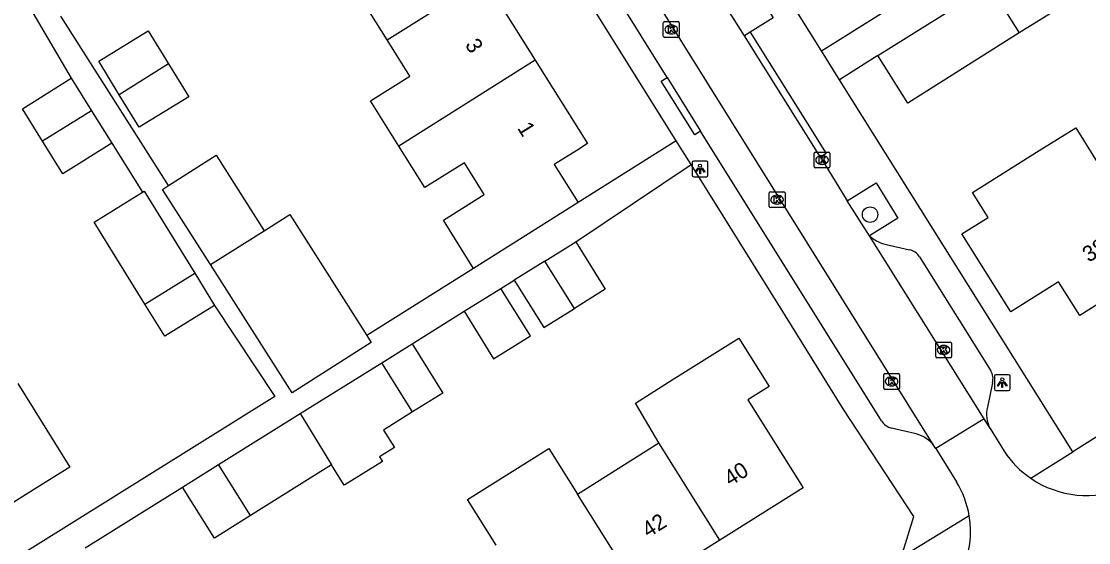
# Model space of a CAD drawing. Extents: x 159353 to 160616, y 385893 to 387321.
# Drawn here: x 159730.6 to 159798.3, y 386120.3 to 386153.3 of the extents above; entities that cross this region are included whole.
import ezdxf

# ---------------------------------------------------------------- set-up
doc = ezdxf.new("R2010")
doc.units = 0
for name, color, linetype in [('IMGEO_Boom', 7, 'Continuous'), ('IMGEO_Kolk', 7, 'Continuous'), ('IMGEO_Lichtpunt', 7, 'Continuous'), ('IMGEO_Pand', 7, 'Continuous'), ('IMGEO_Pand_nummerreeks', 7, 'Continuous'), ('IMGEO_Rijbaan_lokaal_open', 7, 'Continuous'), ('IMGEO_Voetpad_open', 7, 'Continuous')]:
    doc.layers.add(name, color=color, linetype=linetype)

msp = doc.modelspace()

# ---------------------------------------------------------------- linework, layer by layer
at = {"layer": 'IMGEO_Boom'}
msp.add_circle((159784.403, 386141.074), 0.489, dxfattribs=at)
at = {"layer": 'IMGEO_Kolk'}
for p, q in [((159771.291, 386152.384), (159771.291, 386153.236)), ((159771.366, 386153.31), (159772.218, 386153.31)), ((159771.779, 386153.09), (159771.804, 386153.09)), ((159772.292, 386153.236), (159772.292, 386152.384)), ((159772.218, 386152.31), (159771.366, 386152.31)), ((159771.802, 386152.53), (159771.777, 386152.53)), ((159780.853, 386144.115), (159780.853, 386144.967)), ((159780.928, 386145.041), (159781.78, 386145.041)), ((159781.341, 386144.821), (159781.366, 386144.821)), ((159781.854, 386144.967), (159781.854, 386144.115)), ((159781.364, 386144.261), (159781.339, 386144.261)), ((159781.78, 386144.041), (159780.928, 386144.041)), ((159778.006, 386141.598), (159778.006, 386142.45)), ((159778.081, 386142.524), (159778.933, 386142.524)), ((159778.494, 386142.304), (159778.519, 386142.304)), ((159779.007, 386142.45), (159779.007, 386141.598)), ((159778.933, 386141.524), (159778.081, 386141.524)), ((159778.517, 386141.744), (159778.492, 386141.744)), ((159788.563, 386132.072), (159788.563, 386132.924)), ((159788.638, 386132.998), (159789.49, 386132.998)), ((159789.051, 386132.778), (159789.076, 386132.778)), ((159789.564, 386132.924), (159789.564, 386132.072)), ((159789.49, 386131.998), (159788.638, 386131.998)), ((159789.074, 386132.218), (159789.049, 386132.218)), ((159785.265, 386130.071), (159785.265, 386130.923)), ((159785.34, 386130.997), (159786.192, 386130.997)), ((159785.753, 386130.777), (159785.778, 386130.777)), ((159786.266, 386130.923), (159786.266, 386130.071)), ((159786.192, 386129.997), (159785.34, 386129.997)), ((159785.776, 386130.217), (159785.751, 386130.217))]:
    msp.add_line(p, q, dxfattribs=at)
for points in [[(159771.291, 386152.384), (159771.291, 386153.236)], [(159771.366, 386153.31), (159772.218, 386153.31)], [(159771.612, 386153.01), (159771.735, 386153.01), (159771.735, 386152.859), (159771.865, 386153.01), (159772.029, 386153.01), (159771.883, 386152.859), (159772.036, 386152.61), (159771.884, 386152.61), (159771.799, 386152.774), (159771.735, 386152.707), (159771.735, 386152.61), (159771.612, 386152.61), (159771.612, 386153.01)], [(159772.292, 386153.236), (159772.292, 386152.384)], [(159772.218, 386152.31), (159771.366, 386152.31)], [(159780.853, 386144.115), (159780.853, 386144.967)], [(159780.928, 386145.041), (159781.78, 386145.041)], [(159781.854, 386144.967), (159781.854, 386144.115)], [(159781.174, 386144.741), (159781.297, 386144.741), (159781.297, 386144.59), (159781.427, 386144.741), (159781.591, 386144.741), (159781.445, 386144.59), (159781.598, 386144.341), (159781.446, 386144.341), (159781.361, 386144.505), (159781.297, 386144.438), (159781.297, 386144.341), (159781.174, 386144.341), (159781.174, 386144.741)], [(159781.78, 386144.041), (159780.928, 386144.041)], [(159778.006, 386141.598), (159778.006, 386142.45)], [(159778.081, 386142.524), (159778.933, 386142.524)], [(159778.327, 386142.224), (159778.45, 386142.224), (159778.45, 386142.073), (159778.58, 386142.224), (159778.744, 386142.224), (159778.598, 386142.073), (159778.751, 386141.824), (159778.599, 386141.824), (159778.514, 386141.988), (159778.45, 386141.921), (159778.45, 386141.824), (159778.327, 386141.824), (159778.327, 386142.224)], [(159779.007, 386142.45), (159779.007, 386141.598)], [(159778.933, 386141.524), (159778.081, 386141.524)], [(159788.563, 386132.072), (159788.563, 386132.924)], [(159788.638, 386132.998), (159789.49, 386132.998)], [(159788.884, 386132.698), (159789.007, 386132.698), (159789.007, 386132.547), (159789.137, 386132.698), (159789.301, 386132.698), (159789.155, 386132.547), (159789.308, 386132.298), (159789.156, 386132.298), (159789.071, 386132.462), (159789.007, 386132.395), (159789.007, 386132.298), (159788.884, 386132.298), (159788.884, 386132.698)], [(159789.564, 386132.924), (159789.564, 386132.072)], [(159789.49, 386131.998), (159788.638, 386131.998)], [(159785.265, 386130.071), (159785.265, 386130.923)], [(159785.34, 386130.997), (159786.192, 386130.997)], [(159785.586, 386130.697), (159785.709, 386130.697), (159785.709, 386130.546), (159785.839, 386130.697), (159786.003, 386130.697), (159785.857, 386130.546), (159786.01, 386130.297), (159785.858, 386130.297), (159785.773, 386130.461), (159785.709, 386130.394), (159785.709, 386130.297), (159785.586, 386130.297), (159785.586, 386130.697)], [(159786.266, 386130.923), (159786.266, 386130.071)], [(159786.192, 386129.997), (159785.34, 386129.997)]]:
    msp.add_lwpolyline(points, dxfattribs=at)
for centre, start, end in [((159771.368, 386153.234), 91.55205, 178.44795), ((159771.368, 386153.234), 91.55205, 178.44795), ((159772.216, 386153.234), 1.55205, 88.44795), ((159772.216, 386153.234), 1.55205, 88.44795), ((159771.368, 386152.386), 181.55205, 268.44795), ((159771.368, 386152.386), 181.55205, 268.44795), ((159772.216, 386152.386), 271.55205, 358.44795), ((159772.216, 386152.386), 271.55205, 358.44795), ((159780.93, 386144.965), 91.55205, 178.44795), ((159780.93, 386144.965), 91.55205, 178.44795), ((159781.778, 386144.965), 1.55205, 88.44795), ((159781.778, 386144.965), 1.55205, 88.44795), ((159780.93, 386144.117), 181.55205, 268.44795), ((159780.93, 386144.117), 181.55205, 268.44795), ((159781.778, 386144.117), 271.55205, 358.44795), ((159781.778, 386144.117), 271.55205, 358.44795), ((159778.083, 386142.448), 91.55205, 178.44795), ((159778.083, 386142.448), 91.55205, 178.44795), ((159778.931, 386142.448), 1.55205, 88.44795), ((159778.931, 386142.448), 1.55205, 88.44795), ((159778.083, 386141.6), 181.55205, 268.44795), ((159778.083, 386141.6), 181.55205, 268.44795), ((159778.931, 386141.6), 271.55205, 358.44795), ((159778.931, 386141.6), 271.55205, 358.44795), ((159788.64, 386132.922), 91.55205, 178.44795), ((159788.64, 386132.922), 91.55205, 178.44795), ((159789.488, 386132.922), 1.55205, 88.44795), ((159789.488, 386132.922), 1.55205, 88.44795), ((159788.64, 386132.074), 181.55205, 268.44795), ((159788.64, 386132.074), 181.55205, 268.44795), ((159789.488, 386132.074), 271.55205, 358.44795), ((159789.488, 386132.074), 271.55205, 358.44795), ((159785.342, 386130.921), 91.55205, 178.44795), ((159785.342, 386130.921), 91.55205, 178.44795), ((159786.19, 386130.921), 1.55205, 88.44795), ((159786.19, 386130.921), 1.55205, 88.44795), ((159785.342, 386130.073), 181.55205, 268.44795), ((159785.342, 386130.073), 181.55205, 268.44795), ((159786.19, 386130.073), 271.55205, 358.44795), ((159786.19, 386130.073), 271.55205, 358.44795)]:
    msp.add_arc(centre, 0.0765, start, end, dxfattribs=at)
for centre, major_axis, ratio, start_param, end_param in [((159771.778, 386152.81), (-0.387, 0.002), 0.722429, 4.712389, 7.853982), ((159771.803, 386152.81), (-0.39, 0.002), 0.717154, 1.570796, 4.712389), ((159781.34, 386144.541), (-0.387, 0.002), 0.722429, 4.712389, 7.853982), ((159781.365, 386144.541), (-0.39, 0.002), 0.717154, 1.570796, 4.712389), ((159778.493, 386142.024), (-0.387, 0.002), 0.722429, 4.712389, 7.853982), ((159778.518, 386142.024), (-0.39, 0.002), 0.717154, 1.570796, 4.712389), ((159789.05, 386132.498), (-0.387, 0.002), 0.722429, 4.712389, 7.853982), ((159789.075, 386132.498), (-0.39, 0.002), 0.717154, 1.570796, 4.712389), ((159785.752, 386130.497), (-0.387, 0.002), 0.722429, 4.712389, 7.853982), ((159785.777, 386130.497), (-0.39, 0.002), 0.717154, 1.570796, 4.712389)]:
    msp.add_ellipse(centre, major_axis=major_axis, ratio=ratio, start_param=start_param, end_param=end_param, dxfattribs=at)
at = {"layer": 'IMGEO_Lichtpunt'}
for p, q in [((159773.121, 386144.376), (159773.121, 386143.569)), ((159773.121, 386144.376), (159773.121, 386143.569)), ((159774.023, 386144.471), (159773.215, 386144.471)), ((159774.023, 386144.471), (159773.215, 386144.471)), ((159774.117, 386143.569), (159774.117, 386144.376)), ((159774.117, 386143.569), (159774.117, 386144.376)), ((159773.215, 386143.475), (159774.023, 386143.475)), ((159773.215, 386143.475), (159774.023, 386143.475)), ((159792.286, 386130.829), (159792.286, 386130.022)), ((159792.286, 386130.829), (159792.286, 386130.022)), ((159793.188, 386130.924), (159792.38, 386130.924)), ((159793.188, 386130.924), (159792.38, 386130.924)), ((159793.282, 386130.022), (159793.282, 386130.829)), ((159793.282, 386130.022), (159793.282, 386130.829)), ((159792.38, 386129.928), (159793.188, 386129.928)), ((159792.38, 386129.928), (159793.188, 386129.928))]:
    msp.add_line(p, q, dxfattribs=at)
for points in [[(159773.495, 386144.04), (159773.534, 386144.012), (159773.346, 386143.75), (159773.308, 386143.777), (159773.495, 386144.04)], [(159773.597, 386143.992), (159773.644, 386143.992), (159773.644, 386143.67), (159773.597, 386143.67), (159773.597, 386143.992)], [(159773.707, 386144.012), (159773.745, 386144.039), (159773.932, 386143.777), (159773.893, 386143.749), (159773.707, 386144.012)], [(159792.66, 386130.493), (159792.699, 386130.465), (159792.511, 386130.203), (159792.473, 386130.23), (159792.66, 386130.493)], [(159792.762, 386130.445), (159792.809, 386130.445), (159792.809, 386130.123), (159792.762, 386130.123), (159792.762, 386130.445)], [(159792.872, 386130.465), (159792.91, 386130.492), (159793.097, 386130.23), (159793.058, 386130.202), (159792.872, 386130.465)]]:
    msp.add_lwpolyline(points, dxfattribs=at)
for centre in [(159773.62, 386144.174), (159792.785, 386130.627)]:
    msp.add_circle(centre, 0.0994, dxfattribs=at)
for centre, start, end in [((159773.215, 386144.376), 90, 180), ((159773.215, 386144.376), 90, 180), ((159774.023, 386144.376), 0, 90), ((159774.023, 386144.376), 0, 90), ((159773.215, 386143.569), 180, 270), ((159773.215, 386143.569), 180, 270), ((159774.023, 386143.569), 270, 0), ((159774.023, 386143.569), 270, 360), ((159792.38, 386130.829), 90, 180), ((159792.38, 386130.829), 90, 180), ((159793.188, 386130.829), 0, 90), ((159793.188, 386130.829), 0, 90), ((159792.38, 386130.022), 180, 270), ((159792.38, 386130.022), 180, 270), ((159793.188, 386130.022), 270, 0), ((159793.188, 386130.022), 270, 360)]:
    msp.add_arc(centre, 0.0946, start, end, dxfattribs=at)
at = {"layer": 'IMGEO_Pand'}
for points in [[(159795.764, 386157.98), (159797.654, 386154.974), (159793.866, 386152.593)], [(159753.774, 386152.157), (159750.533, 386157.316)], [(159753.774, 386152.157), (159759.928, 386156.026)], [(159759.928, 386156.026), (159763.17, 386150.866)], [(159784.903, 386151.153), (159791.981, 386155.602)], [(159791.981, 386155.602), (159793.866, 386152.593)], [(159736.791, 386148.676), (159735.488, 386150.8), (159738.627, 386152.726), (159739.909, 386150.637)], [(159793.866, 386152.593), (159786.792, 386148.147), (159784.903, 386151.153)], [(159754.513, 386145.424), (159752.714, 386148.286), (159755.222, 386149.853), (159753.774, 386152.157)], [(159763.17, 386150.866), (159754.513, 386145.424)], [(159763.17, 386150.866), (159766.492, 386145.578), (159765.807, 386145.148), (159764.375, 386144.248), (159765.891, 386141.835)], [(159739.909, 386150.637), (159741.191, 386148.547), (159738.052, 386146.621), (159736.791, 386148.676)], [(159739.909, 386150.637), (159736.791, 386148.676)], [(159731.929, 386145.722), (159730.642, 386147.777), (159733.744, 386149.721)], [(159733.744, 386149.721), (159735.037, 386147.657)], [(159735.037, 386147.657), (159731.929, 386145.722)], [(159735.037, 386147.657), (159736.319, 386145.61)], [(159803.004, 386138.009), (159797.698, 386134.685), (159796.362, 386136.818), (159793.319, 386134.911), (159790.22, 386139.858), (159791.884, 386140.9), (159790.896, 386142.477), (159795.134, 386145.132), (159797.447, 386146.58), (159799.02, 386144.068), (159799.155, 386144.152)], [(159736.319, 386145.61), (159733.216, 386143.666), (159731.929, 386145.722)], [(159739.919, 386142.917), (159742.931, 386144.838), (159745.986, 386140.049)], [(159759.254, 386137.665), (159757.34, 386140.715), (159759.939, 386142.345), (159758.677, 386144.353), (159756.169, 386142.787), (159754.513, 386145.424)], [(159742.567, 386137.915), (159739.533, 386142.671), (159739.919, 386142.917)], [(159738.417, 386135.393), (159735.204, 386140.604), (159738.27, 386142.494)], [(159738.27, 386142.494), (159738.372, 386142.557), (159741.575, 386137.36)], [(159765.891, 386141.835), (159761.609, 386139.145), (159759.254, 386137.665)], [(159745.986, 386140.049), (159747.596, 386141.076), (159752.485, 386133.411)], [(159742.567, 386137.915), (159745.986, 386140.049)], [(159763.771, 386138.131), (159765.737, 386139.354)], [(159765.737, 386139.354), (159767.612, 386136.34), (159765.659, 386135.124)], [(159763.771, 386138.131), (159761.83, 386136.923)], [(159765.659, 386135.124), (159763.771, 386138.131)], [(159738.417, 386135.393), (159741.575, 386137.36)], [(159741.575, 386137.36), (159742.836, 386135.315)], [(159752.485, 386133.411), (159752.767, 386132.97), (159747.76, 386129.775), (159742.567, 386137.915)], [(159761.83, 386136.923), (159763.706, 386133.909), (159765.659, 386135.124)], [(159758.652, 386134.945), (159760.981, 386136.395)], [(159758.652, 386134.945), (159760.528, 386131.931), (159762.857, 386133.381), (159760.981, 386136.395)], [(159742.836, 386135.315), (159739.669, 386133.362), (159738.417, 386135.393)], [(159753.43, 386131.683), (159755.354, 386132.884)], [(159755.354, 386132.884), (159757.305, 386129.758), (159755.389, 386128.562)], [(159771.014, 386126.596), (159769.523, 386129.129), (159771.85, 386130.59), (159776.085, 386133.247), (159778.006, 386130.186), (159776.659, 386129.341), (159780.164, 386123.755), (159774.88, 386120.439)], [(159748.261, 386128.457), (159753.43, 386131.683)], [(159755.389, 386128.562), (159753.43, 386131.683)], [(159730.345, 386130.367), (159733.651, 386125.054), (159731.76, 386123.877), (159727.514, 386121.235), (159724.209, 386126.546)], [(159755.389, 386128.562), (159753.551, 386127.415), (159754.238, 386126.315), (159753.291, 386125.724), (159753.473, 386125.433), (159751.093, 386123.947), (159751.053, 386123.922), (159750.253, 386125.205)], [(159743.091, 386125.231), (159748.261, 386128.457)], [(159748.261, 386128.457), (159750.253, 386125.205)], [(159765.852, 386123.357), (159771.014, 386126.596)], [(159774.88, 386120.439), (159771.014, 386126.596)], [(159760.691, 386120.118), (159758.876, 386123.01), (159764.036, 386126.248), (159765.852, 386123.357)], [(159740.8, 386123.801), (159743.091, 386125.231)], [(159745.12, 386122.001), (159743.091, 386125.231)], [(159750.253, 386125.205), (159745.12, 386122.001)], [(159745.12, 386122.001), (159742.819, 386120.566), (159740.8, 386123.801)], [(159769.718, 386117.2), (159765.852, 386123.357)], [(159774.88, 386120.439), (159769.718, 386117.2)]]:
    msp.add_lwpolyline(points, dxfattribs=at)
at = {"layer": 'IMGEO_Rijbaan_lokaal_open'}
for points in [[(159788.47, 386126.403), (159741.92, 386200.989)], [(159776.428, 386152.399), (159773.531, 386157.033)], [(159781.25, 386144.716), (159776.428, 386152.399)], [(159781.25, 386144.716), (159782.945, 386141.957)], [(159784.367, 386139.74), (159782.945, 386141.957)], [(159791.629, 386128.131), (159784.367, 386139.74)], [(159791.629, 386128.131), (159788.572, 386126.24)], [(159792.014, 386127.507), (159791.629, 386128.131)], [(159792.014, 386127.507), (159792.906, 386126.082)], [(159788.572, 386126.24), (159788.47, 386126.403)], [(159788.572, 386126.24), (159789.874, 386124.142)]]:
    msp.add_lwpolyline(points, dxfattribs=at)
for centre, radius, start, end in [((159798.118, 386129.505), 6.235, 213.29516, 235.66648), ((159784.772, 386120.981), 6.001, 9.591, 31.78237), ((159798.129, 386129.516), 6.251, 235.63307, 293.12213), ((159784.775, 386120.98), 6, 302.32867, 9.60808)]:
    msp.add_arc(centre, radius, start, end, dxfattribs=at)
at = {"layer": 'IMGEO_Voetpad_open'}
for points in [[(159781.317, 386151.464), (159745.213, 386209.036), (159745.591, 386210.827)], [(159772.114, 386145.744), (159736.577, 386202.635), (159733.614, 386203.294)], [(159771.528, 386149.758), (159741.852, 386197.34)], [(159773.911, 386157.271), (159775.363, 386158.15), (159778.251, 386153.56), (159776.804, 386152.637)], [(159846.619, 386157.053), (159797.259, 386126.043)], [(159730.165, 386155.842), (159733.744, 386149.721)], [(159781.317, 386151.464), (159788.543, 386155.995)], [(159739.919, 386142.917), (159733.077, 386153.646)], [(159776.804, 386152.637), (159776.428, 386152.399)], [(159776.804, 386152.637), (159781.62, 386144.957), (159781.25, 386144.716)], [(159782.471, 386149.624), (159781.317, 386151.464)], [(159784.903, 386151.153), (159782.471, 386149.624)], [(159773.657, 386146.357), (159773.281, 386146.127), (159771.159, 386149.531), (159771.528, 386149.758)], [(159771.528, 386149.758), (159773.657, 386146.357)], [(159797.259, 386126.043), (159782.471, 386149.624)], [(159785.129, 386127.992), (159773.657, 386146.357)], [(159736.319, 386145.61), (159738.27, 386142.494)], [(159772.114, 386145.744), (159765.891, 386141.835)], [(159773.047, 386144.253), (159772.114, 386145.744)], [(159765.737, 386139.354), (159773.047, 386144.253)], [(159786.376, 386119.338), (159787.187, 386121.946), (159782.701, 386128.77), (159779.029, 386134.648), (159773.047, 386144.253)], [(159782.945, 386141.957), (159784.781, 386143.083), (159786.173, 386140.849), (159784.367, 386139.74)], [(159785.331, 386139.201), (159786.908, 386138.846)], [(159787.534, 386138.408), (159792.055, 386131.179)], [(159759.254, 386137.665), (159752.485, 386133.411)], [(159760.981, 386136.395), (159761.83, 386136.923)], [(159742.836, 386135.315), (159746.659, 386129.537), (159728.985, 386118.536), (159722.272, 386114.357)], [(159755.354, 386132.884), (159758.652, 386134.945)], [(159792.159, 386130.417), (159791.843, 386128.867)], [(159787.323, 386127.175), (159785.757, 386127.54)], [(159794.601, 386124.356), (159797.259, 386126.043)], [(159734.621, 386119.947), (159740.8, 386123.801)], [(159790.69, 386121.981), (159786.376, 386119.338)]]:
    msp.add_lwpolyline(points, dxfattribs=at)
for centre, radius, start, end in [((159785.87, 386141.297), 2.164, 226.00735, 255.57103), ((159786.64, 386137.797), 1.083, 34.35868, 75.68185), ((159791.296, 386130.687), 0.904, 342.6034, 32.94035), ((159793.787, 386128.421), 1.995, 167.07189, 207.2611), ((159786.033, 386128.585), 1.081, 213.28242, 255.22904), ((159786.803, 386125.164), 2.077, 36.61435, 75.4998)]:
    msp.add_arc(centre, radius, start, end, dxfattribs=at)

# ---------------------------------------------------------------- texts
at = {"layer": 'IMGEO_Pand_nummerreeks'}
for s, rotation, p in [('3', 302.13969, (159758.682, 386151.843)), ('1', 302.13969, (159762, 386146.563)), ('38', 32.06463, (159798.268, 386138.016)), ('40', 32.10954, (159775.531, 386123.822)), ('42', 32.10954, (159770.334, 386120.561))]:
    msp.add_text(s, height=1, rotation=rotation, dxfattribs=at).set_placement(p)

doc.saveas('drawing.dxf')
